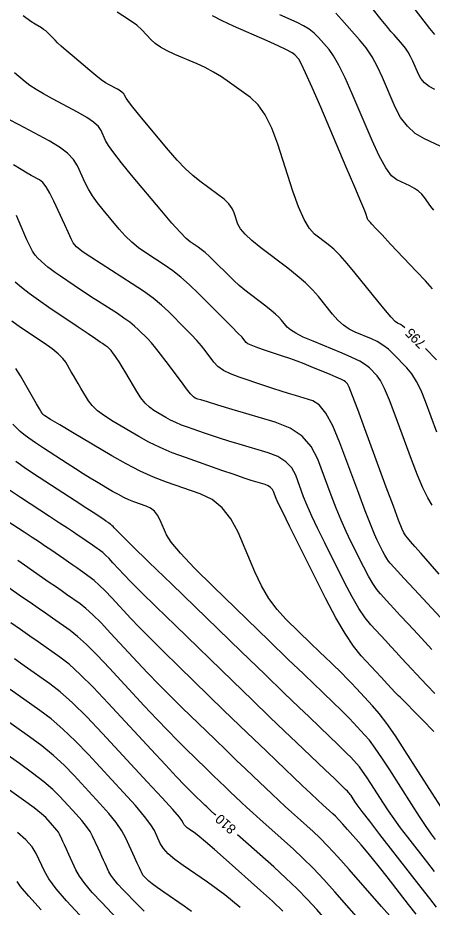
# Model space of a CAD drawing. Extents: x 2082232 to 2083549, y 592624 to 593832.
# Drawn here: x 2082287.6 to 2082317.4, y 593320.2 to 593384.1 of the extents above; entities that cross this region are included whole.
import ezdxf

# ---------------------------------------------------------------- set-up
doc = ezdxf.new("R2010")
doc.units = 0
doc.layers.add('DT_X_Contour_Major', color=7, linetype='Continuous')
doc.layers.add('DT_X_Contour_Minor', color=7, linetype='Continuous')

msp = doc.modelspace()

# ---------------------------------------------------------------- linework, layer by layer
at = {"layer": 'DT_X_Contour_Major'}
for points in [[(2082317.554, 593382.895), (2082317.201, 593383.343), (2082316.14, 593384.689)], [(2082315.41, 593361.838), (2082315.243, 593361.986), (2082315.101, 593362.084), (2082314.865, 593362.181), (2082314.712, 593362.307), (2082314.428, 593362.612), (2082314.015, 593363.097), (2082313.471, 593363.762), (2082311.85, 593365.772), (2082311.272, 593366.467), (2082310.754, 593367.043), (2082310.298, 593367.499), (2082309.901, 593367.837), (2082308.926, 593368.579), (2082308.554, 593368.98), (2082308.172, 593369.628), (2082307.778, 593370.522), (2082307.373, 593371.662), (2082306.28, 593375.03), (2082305.85, 593376.186), (2082305.381, 593377.13), (2082304.873, 593377.86), (2082304.327, 593378.376), (2082302.816, 593379.47), (2082302.246, 593379.861), (2082301.668, 593380.212), (2082301.082, 593380.525), (2082300.489, 593380.798), (2082298.896, 593381.475), (2082298.342, 593381.731), (2082297.875, 593381.992), (2082297.494, 593382.256), (2082297.199, 593382.525), (2082296.53, 593383.248), (2082296.164, 593383.569), (2082295.571, 593383.993), (2082294.75, 593384.517)], [(2082317.331, 593338.76), (2082316.324, 593339.848), (2082315.635, 593340.593), (2082315.072, 593341.202), (2082314.633, 593341.675), (2082314.32, 593342.014), (2082313.652, 593342.736), (2082313.389, 593343.06), (2082313.103, 593343.488), (2082312.792, 593344.022), (2082312.457, 593344.661), (2082311.533, 593346.506), (2082311.184, 593347.232), (2082310.832, 593348.029), (2082310.476, 593348.897), (2082310.116, 593349.834), (2082309.152, 593352.428), (2082308.691, 593353.322), (2082308.03, 593354.06), (2082307.169, 593354.641), (2082306.108, 593355.066), (2082303.013, 593355.989), (2082301.988, 593356.295), (2082301.235, 593356.521), (2082300.753, 593356.666), (2082300.543, 593356.731), (2082300.346, 593356.796), (2082300.23, 593356.887), (2082300.029, 593357.111), (2082299.743, 593357.468), (2082299.373, 593357.957), (2082298.272, 593359.439), (2082297.88, 593359.957), (2082297.529, 593360.397), (2082297.219, 593360.761), (2082296.95, 593361.048), (2082296.288, 593361.71), (2082296.007, 593361.969), (2082295.661, 593362.247), (2082295.249, 593362.545), (2082294.773, 593362.863), (2082293.415, 593363.737), (2082292.924, 593364.055), (2082292.468, 593364.353), (2082292.048, 593364.631), (2082291.663, 593364.889), (2082290.684, 593365.551), (2082290.34, 593365.79), (2082290.04, 593366.009), (2082289.784, 593366.21), (2082289.573, 593366.392), (2082289.07, 593366.853), (2082288.879, 593367.064), (2082288.684, 593367.354), (2082288.483, 593367.722), (2082288.278, 593368.168), (2082287.724, 593369.463), (2082287.525, 593369.901)], [(2082317.683, 593359.537), (2082316.892, 593360.351)], [(2082317.537, 593322.805), (2082317.044, 593323.439), (2082315.613, 593325.285), (2082315.101, 593325.956), (2082314.639, 593326.587), (2082314.228, 593327.176), (2082313.866, 593327.724), (2082312.967, 593329.131), (2082312.651, 593329.616), (2082312.376, 593330.014), (2082312.143, 593330.326), (2082311.952, 593330.552), (2082311.496, 593331.038), (2082311.276, 593331.265), (2082310.958, 593331.58), (2082310.542, 593331.984), (2082310.028, 593332.476), (2082308.527, 593333.907), (2082307.8, 593334.603), (2082306.748, 593335.618), (2082305.37, 593336.951), (2082303.666, 593338.602), (2082298.688, 593343.43), (2082297.043, 593345.027), (2082295.843, 593346.194), (2082295.088, 593346.932), (2082294.778, 593347.242), (2082294.543, 593347.496), (2082294.461, 593347.583), (2082294.389, 593347.654), (2082294.328, 593347.709), (2082294.278, 593347.748), (2082294.159, 593347.832), (2082294.113, 593347.864), (2082294.063, 593347.899), (2082294.009, 593347.937), (2082293.952, 593347.976), (2082293.794, 593348.086), (2082293.621, 593348.2), (2082293.221, 593348.461), (2082292.594, 593348.869), (2082291.74, 593349.423), (2082289.158, 593351.098), (2082288.259, 593351.698), (2082287.495, 593352.242)], [(2082301.828, 593326.853), (2082301.735, 593326.936), (2082301.513, 593327.14), (2082301.183, 593327.455), (2082301.048, 593327.584), (2082300.889, 593327.737), (2082300.707, 593327.912), (2082300.502, 593328.111), (2082299.925, 593328.67), (2082299.592, 593329.01), (2082299.025, 593329.607), (2082298.224, 593330.463), (2082297.19, 593331.578), (2082294.119, 593334.895), (2082293.039, 593336.035), (2082292.101, 593336.966), (2082291.305, 593337.688), (2082290.651, 593338.202), (2082289.096, 593339.294), (2082288.489, 593339.719), (2082287.835, 593340.176), (2082287.132, 593340.664)], [(2082295.56, 593318.586), (2082293.628, 593320.603), (2082292.97, 593321.316), (2082292.446, 593321.943), (2082292.055, 593322.483), (2082291.797, 593322.937), (2082291.289, 593324.034), (2082291.114, 593324.41), (2082290.972, 593324.717), (2082290.862, 593324.955), (2082290.784, 593325.124), (2082290.62, 593325.483), (2082290.543, 593325.625), (2082290.435, 593325.784), (2082290.296, 593325.959), (2082290.127, 593326.15), (2082289.635, 593326.682), (2082289.334, 593326.954), (2082288.798, 593327.374), (2082288.028, 593327.941), (2082287.024, 593328.655)], [(2082317.578, 593310.097), (2082317.049, 593310.612), (2082315.602, 593312.017), (2082315.096, 593312.519), (2082314.663, 593312.971), (2082314.303, 593313.372), (2082314.016, 593313.724), (2082313.349, 593314.596), (2082313.115, 593314.909), (2082312.913, 593315.195), (2082312.743, 593315.454), (2082312.605, 593315.686), (2082312.28, 593316.269), (2082312.094, 593316.551), (2082311.78, 593316.959), (2082311.339, 593317.492), (2082310.77, 593318.151), (2082309.081, 593320.077), (2082308.414, 593320.81), (2082307.678, 593321.564), (2082306.873, 593322.34), (2082305.999, 593323.136), (2082303.577, 593325.289), (2082303.393, 593325.453)]]:
    msp.add_lwpolyline(points, dxfattribs=at)
at = {"layer": 'DT_X_Contour_Minor'}
for points in [[(2082317.55, 593378.959), (2082317.147, 593379.183), (2082316.817, 593379.442), (2082316.559, 593379.737), (2082316.374, 593380.067), (2082315.978, 593380.996), (2082315.82, 593381.333), (2082315.643, 593381.645), (2082315.447, 593381.934), (2082315.231, 593382.199), (2082314.632, 593382.874), (2082314.405, 593383.133), (2082314.173, 593383.406), (2082313.938, 593383.693), (2082313.699, 593383.992), (2082313.055, 593384.808)], [(2082317.692, 593354.35), (2082316.881, 593356.565), (2082316.57, 593357.338), (2082316.244, 593357.997), (2082315.905, 593358.54), (2082315.551, 593358.969), (2082314.589, 593359.959), (2082314.219, 593360.306), (2082313.831, 593360.605), (2082313.424, 593360.856), (2082312.999, 593361.057), (2082311.841, 593361.531), (2082311.414, 593361.746), (2082311, 593362.033), (2082310.6, 593362.394), (2082310.214, 593362.829), (2082309.201, 593364.084), (2082308.778, 593364.565), (2082308.27, 593365.065), (2082307.676, 593365.585), (2082306.997, 593366.125), (2082305.071, 593367.589), (2082304.427, 593368.108), (2082303.939, 593368.565), (2082303.606, 593368.962), (2082303.429, 593369.297), (2082303.165, 593370.111), (2082303.017, 593370.422), (2082302.772, 593370.745), (2082302.43, 593371.08), (2082301.99, 593371.428), (2082300.689, 593372.37), (2082300.182, 593372.775), (2082299.639, 593373.281), (2082299.059, 593373.89), (2082298.443, 593374.601), (2082296.75, 593376.633), (2082296.19, 593377.31), (2082295.778, 593377.819), (2082295.515, 593378.159), (2082295.401, 593378.33), (2082295.296, 593378.562), (2082295.234, 593378.653), (2082295.126, 593378.751), (2082294.973, 593378.857), (2082294.774, 593378.971), (2082294.185, 593379.285), (2082293.932, 593379.438), (2082293.615, 593379.662), (2082293.236, 593379.957), (2082292.793, 593380.322), (2082291.528, 593381.39), (2082291.095, 593381.76), (2082290.747, 593382.066), (2082290.483, 593382.309), (2082290.303, 593382.489), (2082289.935, 593382.886), (2082289.793, 593383.029), (2082289.643, 593383.159), (2082289.485, 593383.276), (2082289.32, 593383.381), (2082288.867, 593383.645), (2082288.569, 593383.846), (2082288.013, 593384.251)], [(2082317.378, 593364.656), (2082316.877, 593365.217), (2082316.244, 593365.896), (2082314.381, 593367.863), (2082313.766, 593368.513), (2082313.321, 593368.985), (2082313.044, 593369.28), (2082312.936, 593369.398), (2082312.873, 593369.476), (2082312.851, 593369.503), (2082312.832, 593369.524), (2082312.818, 593369.539), (2082312.806, 593369.549), (2082312.78, 593369.569), (2082312.768, 593369.586), (2082312.752, 593369.622), (2082312.731, 593369.678), (2082312.706, 593369.752), (2082312.633, 593369.976), (2082312.523, 593370.251), (2082312.248, 593370.909), (2082311.808, 593371.949), (2082311.202, 593373.372), (2082309.367, 593377.677), (2082308.752, 593379.103), (2082308.284, 593380.155), (2082307.963, 593380.831), (2082307.788, 593381.132), (2082307.52, 593381.434), (2082307.319, 593381.582), (2082306.918, 593381.802), (2082306.317, 593382.092), (2082305.516, 593382.453), (2082303.113, 593383.509), (2082302.284, 593383.888), (2082301.597, 593384.234)], [(2082317.478, 593370.289), (2082317.274, 593370.557), (2082316.808, 593371.212), (2082316.611, 593371.447), (2082316.371, 593371.662), (2082316.086, 593371.856), (2082315.758, 593372.03), (2082314.824, 593372.467), (2082314.451, 593372.767), (2082314.031, 593373.341), (2082313.565, 593374.187), (2082313.053, 593375.306), (2082311.625, 593378.656), (2082311.12, 593379.796), (2082310.676, 593380.703), (2082310.294, 593381.378), (2082309.973, 593381.821), (2082309.198, 593382.693), (2082308.885, 593383.005), (2082308.528, 593383.286), (2082308.127, 593383.537), (2082307.682, 593383.758), (2082306.435, 593384.306)], [(2082318.712, 593374.532), (2082316.818, 593375.418), (2082316.154, 593375.809), (2082315.582, 593376.318), (2082315.102, 593376.943), (2082314.714, 593377.687), (2082313.801, 593379.826), (2082313.442, 593380.595), (2082313.048, 593381.299), (2082312.62, 593381.938), (2082312.157, 593382.511), (2082310.876, 593383.953), (2082310.451, 593384.427)], [(2082317.369, 593349.113), (2082317.047, 593349.644), (2082316.692, 593350.366), (2082316.303, 593351.279), (2082315.88, 593352.382), (2082314.71, 593355.579), (2082314.3, 593356.654), (2082313.948, 593357.483), (2082313.655, 593358.065), (2082313.419, 593358.401), (2082312.869, 593358.968), (2082312.591, 593359.193), (2082312.17, 593359.446), (2082311.605, 593359.725), (2082310.897, 593360.031), (2082308.818, 593360.882), (2082308.117, 593361.184), (2082307.573, 593361.454), (2082307.186, 593361.691), (2082306.956, 593361.896), (2082306.551, 593362.397), (2082306.367, 593362.6), (2082306.118, 593362.835), (2082305.804, 593363.101), (2082305.424, 593363.399), (2082304.325, 593364.235), (2082303.917, 593364.556), (2082303.519, 593364.893), (2082303.129, 593365.246), (2082302.748, 593365.615), (2082301.744, 593366.618), (2082301.388, 593366.965), (2082301.073, 593367.252), (2082300.799, 593367.478), (2082300.565, 593367.646), (2082299.997, 593368.011), (2082299.71, 593368.253), (2082299.273, 593368.702), (2082298.688, 593369.36), (2082297.954, 593370.226), (2082295.799, 593372.814), (2082295.076, 593373.697), (2082294.524, 593374.405), (2082294.143, 593374.939), (2082293.934, 593375.298), (2082293.604, 593376.023), (2082293.409, 593376.308), (2082293.071, 593376.616), (2082292.592, 593376.949), (2082291.97, 593377.305), (2082290.122, 593378.29), (2082289.48, 593378.643), (2082288.939, 593378.965), (2082288.499, 593379.255), (2082288.161, 593379.514), (2082287.394, 593380.161)], [(2082317.876, 593344.151), (2082316.567, 593345.639), (2082316.131, 593346.137), (2082315.803, 593346.515), (2082315.584, 593346.774), (2082315.475, 593346.913), (2082315.327, 593347.124), (2082315.207, 593347.389), (2082314.957, 593348.025), (2082314.578, 593349.034), (2082314.069, 593350.415), (2082312.539, 593354.593), (2082312.03, 593355.971), (2082311.652, 593356.97), (2082311.405, 593357.591), (2082311.287, 593357.833), (2082311.149, 593357.976), (2082311.04, 593358.048), (2082310.819, 593358.159), (2082310.484, 593358.308), (2082310.037, 593358.496), (2082308.692, 593359.046), (2082308.184, 593359.249), (2082307.669, 593359.444), (2082307.147, 593359.632), (2082306.618, 593359.813), (2082305.197, 593360.285), (2082304.724, 593360.449), (2082304.368, 593360.59), (2082304.132, 593360.706), (2082304.013, 593360.798), (2082303.855, 593361.012), (2082303.719, 593361.166), (2082303.43, 593361.468), (2082302.988, 593361.918), (2082302.392, 593362.515), (2082300.601, 593364.306), (2082299.948, 593364.937), (2082299.331, 593365.483), (2082298.751, 593365.947), (2082298.207, 593366.327), (2082296.805, 593367.229), (2082296.291, 593367.59), (2082295.802, 593367.995), (2082295.335, 593368.445), (2082294.893, 593368.94), (2082293.744, 593370.318), (2082293.342, 593370.828), (2082292.994, 593371.322), (2082292.703, 593371.802), (2082292.467, 593372.266), (2082291.911, 593373.485), (2082291.628, 593373.939), (2082291.194, 593374.386), (2082290.61, 593374.827), (2082289.876, 593375.261), (2082287.718, 593376.411), (2082286.986, 593376.803)], [(2082320.088, 593338.745), (2082316.1, 593343.053), (2082315.358, 593343.855), (2082314.868, 593344.384), (2082314.632, 593344.639), (2082314.34, 593344.955), (2082314.225, 593345.097), (2082314.099, 593345.285), (2082313.963, 593345.518), (2082313.817, 593345.798), (2082313.412, 593346.606), (2082313.215, 593347.042), (2082312.93, 593347.744), (2082312.555, 593348.713), (2082312.091, 593349.949), (2082310.734, 593353.6), (2082310.231, 593354.815), (2082309.739, 593355.723), (2082309.259, 593356.322), (2082308.79, 593356.614), (2082307.555, 593356.983), (2082307.066, 593357.131), (2082306.526, 593357.301), (2082305.934, 593357.492), (2082305.29, 593357.704), (2082303.504, 593358.297), (2082302.889, 593358.531), (2082302.382, 593358.79), (2082301.983, 593359.072), (2082301.693, 593359.378), (2082301.064, 593360.226), (2082300.8, 593360.561), (2082300.479, 593360.932), (2082300.103, 593361.339), (2082299.671, 593361.782), (2082298.444, 593363.008), (2082297.937, 593363.478), (2082297.335, 593363.968), (2082296.639, 593364.478), (2082295.848, 593365.008), (2082293.613, 593366.447), (2082292.873, 593366.927), (2082292.33, 593367.288), (2082291.982, 593367.53), (2082291.831, 593367.653), (2082291.69, 593367.823), (2082291.607, 593367.958), (2082291.465, 593368.239), (2082291.262, 593368.664), (2082290.999, 593369.234), (2082290.219, 593370.947), (2082289.935, 593371.524), (2082289.668, 593371.97), (2082289.417, 593372.286), (2082289.183, 593372.471), (2082288.582, 593372.791), (2082288.292, 593372.954), (2082287.871, 593373.203), (2082287.32, 593373.538)], [(2082317.564, 593335.603), (2082317.007, 593336.162), (2082316.568, 593336.623), (2082315.553, 593337.719), (2082315.171, 593338.132), (2082314.786, 593338.548), (2082314.398, 593338.967), (2082314.008, 593339.389), (2082312.964, 593340.517), (2082312.554, 593341.023), (2082312.106, 593341.692), (2082311.621, 593342.526), (2082311.098, 593343.525), (2082309.653, 593346.406), (2082309.153, 593347.423), (2082308.734, 593348.315), (2082308.397, 593349.08), (2082308.142, 593349.719), (2082307.571, 593351.256), (2082307.286, 593351.789), (2082306.86, 593352.236), (2082306.294, 593352.598), (2082305.586, 593352.873), (2082303.51, 593353.492), (2082302.772, 593353.715), (2082302.113, 593353.92), (2082301.535, 593354.108), (2082301.037, 593354.277), (2082299.815, 593354.705), (2082299.374, 593354.869), (2082298.967, 593355.04), (2082298.594, 593355.219), (2082298.255, 593355.406), (2082297.398, 593355.913), (2082297.079, 593356.142), (2082296.767, 593356.446), (2082296.462, 593356.827), (2082296.163, 593357.284), (2082295.375, 593358.603), (2082295.107, 593359.049), (2082294.895, 593359.394), (2082294.739, 593359.641), (2082294.639, 593359.787), (2082294.447, 593360.046), (2082294.379, 593360.136), (2082294.321, 593360.21), (2082294.271, 593360.27), (2082294.229, 593360.314), (2082294.131, 593360.412), (2082294.089, 593360.451), (2082294.038, 593360.492), (2082293.977, 593360.536), (2082293.906, 593360.583), (2082293.705, 593360.713), (2082293.54, 593360.822), (2082293.195, 593361.054), (2082292.671, 593361.408), (2082291.966, 593361.884), (2082289.849, 593363.315), (2082289.104, 593363.832), (2082288.455, 593364.307), (2082287.902, 593364.742), (2082287.446, 593365.136)], [(2082317.477, 593332.868), (2082316.64, 593333.732), (2082316.009, 593334.381), (2082315.585, 593334.814), (2082315.366, 593335.031), (2082315.059, 593335.322), (2082314.956, 593335.418), (2082314.881, 593335.491), (2082314.831, 593335.538), (2082314.808, 593335.562), (2082314.781, 593335.59), (2082314.706, 593335.672), (2082314.163, 593336.258), (2082313.696, 593336.763), (2082312.277, 593338.298), (2082311.719, 593338.985), (2082311.11, 593339.896), (2082310.45, 593341.03), (2082309.739, 593342.388), (2082307.774, 593346.306), (2082307.121, 593347.614), (2082306.636, 593348.6), (2082306.318, 593349.263), (2082306.167, 593349.604), (2082305.989, 593350.084), (2082305.9, 593350.25), (2082305.768, 593350.39), (2082305.591, 593350.503), (2082305.37, 593350.588), (2082304.722, 593350.782), (2082304.387, 593350.888), (2082303.867, 593351.062), (2082303.163, 593351.304), (2082302.273, 593351.614), (2082299.657, 593352.53), (2082298.712, 593352.881), (2082297.84, 593353.249), (2082297.042, 593353.632), (2082296.316, 593354.032), (2082294.479, 593355.118), (2082293.851, 593355.517), (2082293.345, 593355.898), (2082292.96, 593356.262), (2082292.697, 593356.609), (2082292.159, 593357.51), (2082291.964, 593357.838), (2082291.783, 593358.145), (2082291.615, 593358.431), (2082291.462, 593358.697), (2082291.071, 593359.377), (2082290.863, 593359.654), (2082290.535, 593359.974), (2082290.086, 593360.336), (2082289.516, 593360.741), (2082287.834, 593361.878), (2082287.204, 593362.323)], [(2082318.017, 593327.425), (2082317.363, 593328.442), (2082315.414, 593331.494), (2082314.721, 593332.554), (2082314.101, 593333.443), (2082313.555, 593334.163), (2082313.083, 593334.713), (2082311.922, 593335.952), (2082311.521, 593336.378), (2082311.189, 593336.725), (2082310.926, 593336.995), (2082310.732, 593337.186), (2082310.306, 593337.592), (2082310.082, 593337.806), (2082309.732, 593338.144), (2082309.255, 593338.606), (2082308.651, 593339.191), (2082306.871, 593340.918), (2082306.231, 593341.617), (2082305.645, 593342.42), (2082305.113, 593343.326), (2082304.635, 593344.336), (2082303.433, 593347.168), (2082302.926, 593348.137), (2082302.304, 593348.92), (2082301.569, 593349.517), (2082300.719, 593349.927), (2082298.302, 593350.773), (2082297.377, 593351.129), (2082296.414, 593351.561), (2082295.414, 593352.071), (2082294.377, 593352.657), (2082291.56, 593354.323), (2082290.634, 593354.873), (2082289.968, 593355.274), (2082289.561, 593355.527), (2082289.414, 593355.63), (2082289.368, 593355.707), (2082289.312, 593355.803), (2082289.18, 593356.032), (2082288.97, 593356.396), (2082288.685, 593356.893), (2082287.82, 593358.398), (2082287.493, 593358.921)], [(2082317.608, 593325.099), (2082317.314, 593325.498), (2082316.934, 593326.051), (2082316.466, 593326.757), (2082315.912, 593327.617), (2082314.318, 593330.113), (2082313.758, 593330.972), (2082313.27, 593331.679), (2082312.857, 593332.232), (2082312.517, 593332.632), (2082311.709, 593333.495), (2082311.399, 593333.821), (2082311.074, 593334.153), (2082310.734, 593334.489), (2082310.38, 593334.831), (2082309.416, 593335.75), (2082308.911, 593336.234), (2082308.119, 593336.999), (2082307.04, 593338.043), (2082305.673, 593339.367), (2082301.647, 593343.272), (2082300.305, 593344.602), (2082299.299, 593345.665), (2082298.629, 593346.459), (2082298.295, 593346.986), (2082297.85, 593348.032), (2082297.663, 593348.39), (2082297.433, 593348.68), (2082297.161, 593348.9), (2082296.848, 593349.052), (2082295.954, 593349.364), (2082295.608, 593349.499), (2082295.238, 593349.667), (2082294.845, 593349.869), (2082294.428, 593350.105), (2082293.286, 593350.781), (2082292.832, 593351.054), (2082292.328, 593351.366), (2082291.771, 593351.717), (2082291.164, 593352.108), (2082289.477, 593353.203), (2082288.898, 593353.586), (2082288.427, 593353.915), (2082288.063, 593354.189), (2082287.808, 593354.409), (2082287.271, 593354.921)], [(2082317.668, 593320.262), (2082317.186, 593320.875), (2082316.568, 593321.668), (2082315.813, 593322.639), (2082313.618, 593325.47), (2082312.888, 593326.414), (2082312.345, 593327.122), (2082311.989, 593327.595), (2082311.819, 593327.832), (2082311.616, 593328.15), (2082311.544, 593328.26), (2082311.482, 593328.35), (2082311.43, 593328.42), (2082311.386, 593328.471), (2082311.283, 593328.581), (2082311.154, 593328.708), (2082310.843, 593329.007), (2082310.351, 593329.478), (2082309.676, 593330.121), (2082307.637, 593332.065), (2082306.776, 593332.889), (2082305.721, 593333.904), (2082304.474, 593335.108), (2082303.034, 593336.504), (2082298.935, 593340.478), (2082297.553, 593341.823), (2082296.48, 593342.877), (2082295.715, 593343.639), (2082295.26, 593344.109), (2082294.458, 593344.975), (2082294.176, 593345.273), (2082293.931, 593345.516), (2082293.723, 593345.705), (2082293.553, 593345.839), (2082293.147, 593346.124), (2082292.988, 593346.235), (2082292.817, 593346.355), (2082292.634, 593346.482), (2082292.438, 593346.618), (2082291.899, 593346.991), (2082291.623, 593347.177), (2082291.201, 593347.457), (2082290.632, 593347.829), (2082289.916, 593348.295), (2082287.812, 593349.659), (2082287.041, 593350.184)], [(2082316.204, 593319.75), (2082315.656, 593320.454), (2082314.13, 593322.423), (2082313.584, 593323.12), (2082313.09, 593323.737), (2082312.649, 593324.272), (2082312.261, 593324.725), (2082311.295, 593325.827), (2082310.957, 593326.207), (2082310.665, 593326.523), (2082310.421, 593326.774), (2082310.224, 593326.961), (2082309.762, 593327.372), (2082309.524, 593327.589), (2082309.157, 593327.932), (2082308.66, 593328.401), (2082308.035, 593328.996), (2082306.195, 593330.749), (2082305.44, 593331.471), (2082304.556, 593332.321), (2082303.543, 593333.299), (2082302.401, 593334.405), (2082299.183, 593337.526), (2082298.063, 593338.62), (2082297.116, 593339.559), (2082296.343, 593340.345), (2082295.743, 593340.976), (2082294.374, 593342.455), (2082293.892, 593342.964), (2082293.474, 593343.379), (2082293.119, 593343.701), (2082292.827, 593343.93), (2082292.134, 593344.417), (2082291.863, 593344.606), (2082291.572, 593344.81), (2082291.258, 593345.028), (2082290.924, 593345.259), (2082290.003, 593345.896), (2082289.625, 593346.155), (2082289.181, 593346.453), (2082288.67, 593346.79), (2082288.093, 593347.166), (2082286.466, 593348.221)], [(2082314.506, 593319.404), (2082313.729, 593320.292), (2082311.4, 593322.949), (2082310.583, 593323.868), (2082309.88, 593324.63), (2082309.291, 593325.236), (2082308.816, 593325.686), (2082307.7, 593326.678), (2082307.272, 593327.063), (2082306.822, 593327.475), (2082306.352, 593327.913), (2082305.861, 593328.377), (2082304.524, 593329.651), (2082303.976, 593330.176), (2082303.334, 593330.793), (2082302.598, 593331.504), (2082301.768, 593332.307), (2082299.43, 593334.574), (2082298.572, 593335.416), (2082297.752, 593336.242), (2082296.97, 593337.051), (2082296.225, 593337.844), (2082294.289, 593339.935), (2082293.608, 593340.654), (2082293.016, 593341.241), (2082292.514, 593341.696), (2082292.102, 593342.02), (2082291.121, 593342.709), (2082290.739, 593342.977), (2082290.326, 593343.265), (2082289.883, 593343.573), (2082289.41, 593343.901), (2082288.108, 593344.802), (2082287.627, 593345.132)], [(2082312.598, 593318.824), (2082310.39, 593321.343), (2082309.582, 593322.243), (2082308.816, 593323.054), (2082308.091, 593323.777), (2082307.407, 593324.411), (2082305.639, 593325.984), (2082305.019, 593326.537), (2082304.487, 593327.017), (2082304.043, 593327.424), (2082303.687, 593327.759), (2082302.853, 593328.553), (2082302.512, 593328.88), (2082302.111, 593329.265), (2082301.653, 593329.708), (2082301.135, 593330.209), (2082299.678, 593331.622), (2082299.082, 593332.213), (2082298.389, 593332.925), (2082297.597, 593333.757), (2082296.707, 593334.711), (2082294.204, 593337.415), (2082293.323, 593338.344), (2082292.558, 593339.103), (2082291.909, 593339.692), (2082291.376, 593340.111), (2082290.109, 593341.001), (2082289.614, 593341.348), (2082289.08, 593341.72), (2082288.508, 593342.119), (2082287.896, 593342.542), (2082286.213, 593343.707)], [(2082306.652, 593319.973), (2082305.909, 593320.676), (2082305.043, 593321.459), (2082302.571, 593323.656), (2082301.739, 593324.392), (2082301.097, 593324.95), (2082300.644, 593325.331), (2082300.381, 593325.534), (2082299.933, 593325.841), (2082299.781, 593325.953), (2082299.66, 593326.057), (2082299.572, 593326.155), (2082299.516, 593326.247), (2082299.408, 593326.481), (2082299.222, 593326.72), (2082298.746, 593327.263), (2082297.979, 593328.108), (2082296.921, 593329.257), (2082293.713, 593332.723), (2082292.574, 593333.921), (2082291.563, 593334.915), (2082290.68, 593335.706), (2082289.925, 593336.293), (2082288.084, 593337.586), (2082287.388, 593338.073)], [(2082303.577, 593320.235), (2082303.045, 593320.691), (2082302.477, 593321.146), (2082301.874, 593321.598), (2082301.235, 593322.048), (2082299.484, 593323.245), (2082298.889, 593323.68), (2082298.42, 593324.09), (2082298.075, 593324.473), (2082297.855, 593324.829), (2082297.435, 593325.744), (2082297.178, 593326.172), (2082296.724, 593326.771), (2082296.072, 593327.54), (2082295.223, 593328.48), (2082292.693, 593331.212), (2082291.764, 593332.179), (2082290.872, 593333.03), (2082290.017, 593333.765), (2082289.2, 593334.383), (2082287.071, 593335.878)], [(2082300.099, 593319.934), (2082299.558, 593320.315), (2082298.12, 593321.33), (2082297.64, 593321.672), (2082297.277, 593321.937), (2082297.032, 593322.125), (2082296.904, 593322.236), (2082296.719, 593322.429), (2082296.656, 593322.498), (2082296.605, 593322.558), (2082296.568, 593322.609), (2082296.543, 593322.653), (2082296.495, 593322.758), (2082296.45, 593322.855), (2082296.351, 593323.069), (2082296.2, 593323.4), (2082295.994, 593323.847), (2082295.376, 593325.194), (2082295.086, 593325.729), (2082294.681, 593326.326), (2082294.16, 593326.984), (2082293.524, 593327.703), (2082291.674, 593329.702), (2082290.954, 593330.438), (2082290.18, 593331.145), (2082289.354, 593331.823), (2082288.474, 593332.474), (2082286.059, 593334.171)], [(2082296.698, 593319.964), (2082296.232, 593320.411), (2082295.173, 593321.516), (2082294.813, 593321.907), (2082294.525, 593322.25), (2082294.311, 593322.546), (2082294.17, 593322.795), (2082293.892, 593323.396), (2082293.782, 593323.633), (2082293.662, 593323.893), (2082293.531, 593324.178), (2082293.389, 593324.486), (2082292.998, 593325.338), (2082292.814, 593325.677), (2082292.558, 593326.055), (2082292.228, 593326.471), (2082291.826, 593326.927), (2082290.655, 593328.192), (2082290.144, 593328.696), (2082289.489, 593329.26), (2082288.691, 593329.882), (2082287.749, 593330.565), (2082285.046, 593332.463)], [(2082292.082, 593319.689), (2082291.134, 593320.71), (2082290.394, 593321.575), (2082289.861, 593322.284), (2082289.537, 593322.837), (2082288.948, 593324.106), (2082288.652, 593324.591), (2082288.204, 593325.095), (2082287.604, 593325.617)], [(2082289.317, 593320.064), (2082288.416, 593321.047), (2082287.834, 593321.726), (2082287.572, 593322.1)]]:
    msp.add_lwpolyline(points, dxfattribs=at)

# ---------------------------------------------------------------- texts
at = {"layer": 'DT_X_Contour_Major'}
for s, rotation, p in [('795', 134.90605, (2082316.969, 593360.786)), ('810', 138.20569, (2082303.356, 593325.954))]:
    msp.add_text(s, height=0.7, rotation=rotation, dxfattribs=at).set_placement(p)

doc.saveas('drawing.dxf')
